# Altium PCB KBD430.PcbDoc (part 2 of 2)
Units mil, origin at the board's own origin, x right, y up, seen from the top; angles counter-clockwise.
Board outline 5000 x 5500 mil, 4 copper layers (Top Layer, Ground Plane, Power Plane, Bottom Layer), stack 90 mil thick; 72 components, 94 nets, 353 pads, 293 vias.
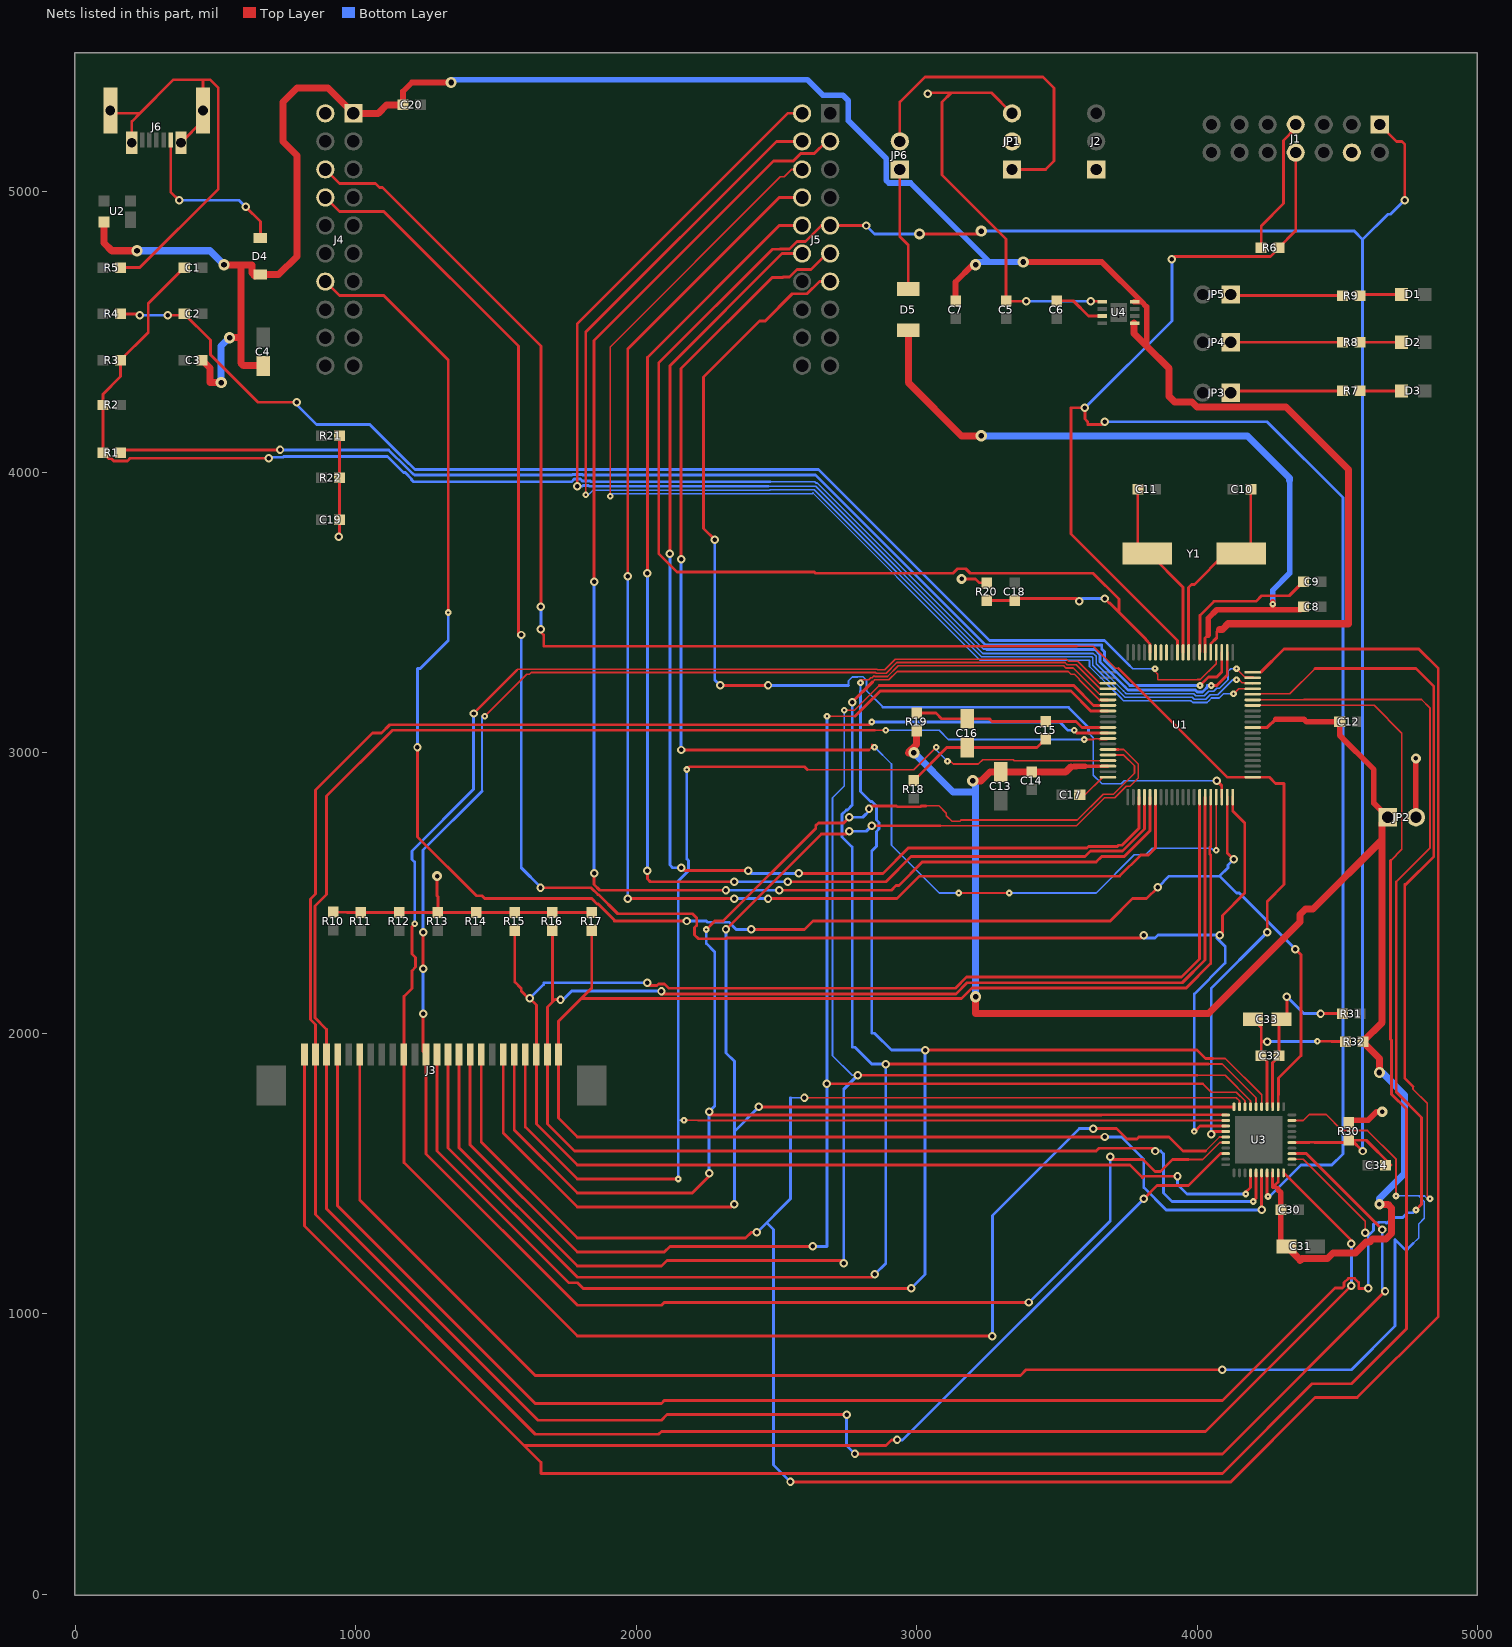
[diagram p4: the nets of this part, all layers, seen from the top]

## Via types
v1: diameter 30, hole 16, Top Layer to Bottom Layer, 176 vias
v2: diameter 24, hole 8, Top Layer to Bottom Layer, 68 vias
v3: diameter 25.98, hole 12.99, Top Layer to Bottom Layer, tented top, 16 vias
v4: diameter 40, hole 20, Top Layer to Bottom Layer, 14 vias
v5: diameter 36, hole 16, Top Layer to Bottom Layer, 13 vias
v6: diameter 32, hole 16, Top Layer to Bottom Layer, 2 vias
v7: diameter 28, hole 16, Top Layer to Bottom Layer, 2 vias
v8: diameter 36, hole 16, Top Layer to Bottom Layer, tented top, 1 vias
v9: diameter 36, hole 16, Top Layer to Bottom Layer, tented both sides, 1 vias

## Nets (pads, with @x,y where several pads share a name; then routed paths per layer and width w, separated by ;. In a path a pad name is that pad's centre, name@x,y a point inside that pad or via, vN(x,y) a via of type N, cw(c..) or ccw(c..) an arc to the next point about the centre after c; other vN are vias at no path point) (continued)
KSI5: J3.22 R15.1 U1.34 U3.34 | length 6521.6
  Top Layer w10: R15.1@1567.14,2367.2 1567.14,2182.86 1590,2160 1590,2150 1615.98,2124.02 v1(1620,2124.02) 1644.02,2100 J3.22@1644.02,1924 1644.02,1675.98 1790,1530 3760,1530 3805,1485 3810,1490 v1(3930,1490) ; v1(2040,2180) 2040,2170 2073.23,2170 2079.23,2176 2100.77,2176 2116.77,2160 3137.37,2160 3177.37,2200 3944.54,2200 4008.9,2264.36 U1.34@4008.9,2842.13 ; v2(4173.38,1426.62) 4170,1430 4190.46,1450.46 U3.34@4190.46,1502.87
  Bottom Layer w10: v1(1620,2124.02) 1670,2174.02 1670,2180 v1(2040,2180) ; v1(3930,1490) 3930,1460 3963.38,1426.62 v2(4173.38,1426.62)
KSI6: J3.23 R16.1 U1.35 U3.35 | length 6490.9
  Top Layer w10: 1701.3,2111.3 R16.1@1701.3,2367.2 ; v1(1730,2120) 1710,2120 1683.39,2093.39 J3.23@1683.39,1924 1683.39,1676.61 1780,1580 3640,1580 3650,1590 3840,1590 v1(3850,1580) ; v1(2090,2150) 2090,2140 3140,2140 3180,2180 3947.16,2180 4028.58,2261.42 U1.35@4028.58,2842.13 ; v2(4200,1400) 4210.15,1410.15 U3.35@4210.15,1502.87
  Bottom Layer w10: v1(1730,2120) 1740,2120 1770,2150 v1(2090,2150) ; 3870,1580 3880,1570 3880,1430 3910,1400 v2(4200,1400)
KSI7: J3.24 R17.1 U1.36 U3.36 | length 6445.5
  Top Layer w10: R17.1@1841.43,2367.2 1841.43,2161.43 1804,2124 ; v1(3670,1630) 1790,1630 1722.76,1697.24 J3.24@1722.76,1924 1722.76,2042.76 1804,2124 ; U1.36@4048.27,2842.13 4048.27,2664.89 4044.95,2661.57 4044.95,2639.21 4048.27,2635.89 4048.27,2248.27 3961,2161 3197.16,2161 3160.16,2124 1804,2124 ; v1(4229.84,1370.16) U3.36@4229.84,1502.87
  Bottom Layer w10: v1(3670,1630) 3730,1630 3810,1550 3810,1450 3890,1370 4200,1370 4200.16,1370.16 v1(4229.84,1370.16)
KSO0: J3.1 U1.54 U3.28 | length 10814
  Top Layer w6: U1.54@4197.87,3168.9 4631.1,3168.9 4730,3070 4730,2655.41 4690,2615.41
  Top Layer w10: J3.1@817.24,1924 817.24,1312.76 1600,530 ; v1(2930,550) 2910,550 2890,530 1600,530 ; v1(3810,1410) 3856.8,1456.8 3969.61,1456.8 4083.6,1570.79 U3.28@4102.87,1570.79 ; 4690,2615.41 4690,1978.67 4693.2,1975.47 4693.2,1782.42 4746.4,1729.22 4746.4,946.4 4550,750 4410,750 4090,430 1660,430 1660,470 1600,530
  Bottom Layer w10: v1(2930,550) 2950,550 v1(3810,1410)
KSO1: J3.2 U1.12 U3.40 | length 9211.2
  Top Layer w10: v2(2840,3110) 2830,3100 1121.33,3100 1091.33,3070 1060,3070 856.61,2866.61 856.61,2496.08 838.53,2477.99 838.53,2048.72 856.61,2030.63 J3.2@856.61,1924 856.61,1353.39 1640,570 2080,570 2090,580 4030,580 v1(4550,1100) ; v2(3561.89,3080) 3570.94,3070.94 3580,3070.94 3580.47,3070.47 U1.12@3682.13,3070.47 ; U3.40@4308.6,1502.87 4550,1261.48 v1(4550,1250)
  Bottom Layer w10: v2(2840,3110) 3510,3110 3540,3080 v2(3561.89,3080) ; v1(4550,1100) v1(4550,1250)
KSO2: J3.3 U1.13 U3.3 | length 9522.9
  Top Layer w6: 2850,3080 v2(2890,3080) ; v2(3597.36,3047.47) 3630.6,3047.47 3633.23,3050.1 3648.97,3050.1 3651.6,3047.47 3678.81,3047.47 U1.13@3682.13,3050.79
  Top Layer w10: v1(2750,640) 2110,640 2090,620 1650,620 895.98,1374.02 J3.3@895.98,1924 895.98,2013.89 854.53,2055.35 854.53,2453.28 895.98,2494.73 895.98,2845.98 1130,3080 2850,3080 ; v1(2780,500) 4090,500 v1(4670,1080) ; U3.3@4337.13,1570.79 4389.21,1570.79 v1(4660,1300)
  Bottom Layer w6: v2(2890,3080) 3080,3080 3112.53,3047.47 v2(3597.36,3047.47)
  Bottom Layer w10: v1(2750,640) 2750,530 v1(2780,500) ; v1(4660,1300) 4660,1090 v1(4670,1080)
KSO3: J3.4 U1.55 U3.2 | length 8064
  Top Layer w6: U1.55@4197.87,3188.58 4378.58,3188.58 4380,3190 4800,3190 4830,3160 4830,2660.06 4709.94,2540 ; U3.2@4337.13,1551.1 4378.9,1551.1 4600,1330 v1(4600,1288.23)
  Top Layer w10: J3.4@935.35,1924 935.35,1384.65 1640,680 2090,680 2100,690 4090,690 4491.31,1091.31 4518.69,1091.31 4524,1096.63 4524,1110.77 4539.23,1126 4560.77,1126 4576,1110.77 4576,1090 v1(4610,1090) ; 4709.94,2540 4709.94,1790.06 4800,1700 4800,1390 v2(4780,1370)
  Bottom Layer w10: v1(4610,1090) 4610,1278.23 4628.57,1296.8 4628.57,1318.57 4633.2,1323.2 4646.43,1323.2 4649.23,1326 4670.77,1326 4673.57,1323.2 4676.41,1323.2 4696.41,1343.2 4733.2,1343.2 4750,1360 4770,1360 v2(4780,1370)
KSO4: J3.6 U1.56 U3.9 | length 8456.1
  Top Layer w6: U1.56@4197.87,3208.27 4199.61,3210 4330,3210 4420,3300 ; U3.9@4337.13,1688.9 4378.9,1688.9 4400,1710 4460.38,1710 4517.57,1652.81 4607.19,1652.81 4709.39,1550.61 v2(4709.39,1419.39) ; 4770,1810 4770,1800 4820,1750 4820,1420 v2(4830,1410)
  Top Layer w10: J3.6@1014.09,1924 1014.09,1405.91 1640,780 3370,780 3390,800 v1(4090,800) ; 4420,3300 4780,3300 4844,3236 4844,2630 4744,2530 4740,2530 4740,1840 4770,1810
  Bottom Layer w6: v2@4719.39,1420 4790,1420 ; 4770,1250 4790,1270 4790,1320 4810,1340 4810,1400 4790.61,1419.39 4810.61,1419.39 4830,1400 v2(4830,1410)
  Bottom Layer w10: v1(4090,800) 4550,800 4706.02,956.02 4706.02,1263.98 4740,1230 4750,1230 4770,1250
KSO5: J3.10 U1.3 U3.25 | length 7908.8
  Top Layer w6: 1572.8,3292.8 1578.03,3298.03 2858.03,3298.03 2860.06,3296 2886,3296 2924,3334 3534,3334 3542,3326 3574,3326 3652.36,3247.64 U1.3@3682.13,3247.64 ; 4030,1580 4079.84,1629.84 U3.25@4102.87,1629.84
  Top Layer w10: v2(1210,2390) 1200,2380 1200,2282.81 1213.2,2269.61 1213.2,2235.62 1200,2222.42 1200,2160 1171.57,2131.57 J3.10@1171.57,1924 1171.57,1538.43 1790,920 v1(3270,920) ; v1(1420,3140) 1572.8,3292.8 ; v1(3630,1660) 3712.81,1660 3749.61,1623.2 3785.47,1623.2 3792.11,1629.84 3900.16,1629.84 3950,1580 4030,1580
  Bottom Layer w10: v2(1210,2390) 1210,2610 1200,2620 1200,2650 1420,2870 v1(1420,3140) ; v1(3270,920) 3270,1350 3580,1660 v1(3630,1660)
KSO6: J3.12 U1.4 U3.26 | length 7505.3
  Top Layer w6: v2(1460,3130) 1610,3280 1619.2,3280 1619.6,3279.6 1626.03,3286.03 2853.06,3286.03 2855.09,3284 2890.97,3284 2928.97,3322 3529.03,3322 3537.03,3314 3569.03,3314 3655.08,3227.95 U1.4@3682.13,3227.95 ; 3968.52,1550 4020,1550 4080.16,1610.16 U3.26@4102.87,1610.16
  Top Layer w10: v1(1240,2070) 1240,1934.32 J3.12@1250.32,1924 1250.32,1569.68 1790,1030 2090,1030 2100,1040 v1(3400,1040) ; v1(1240,2230) v1(1240,2360) ; v1(3690,1560) 3690,1550 3807.19,1550 3850.39,1506.8 3869.61,1506.8 3912.81,1550 3968.52,1550
  Bottom Layer w6: 1450,2862.81 1450,3130 v2(1460,3130)
  Bottom Layer w10: v1(1240,2070) v1(1240,2230) ; v1(1240,2360) 1240,2652.81 1450,2862.81 ; v1(3400,1040) 3690,1330 v1(3690,1560)
KSO7: J3.13 U1.5 U3.15 | length 6879.6
  Top Layer w6: v2(2800,3250) 2800,3260 2829.26,3260 2829.26,3260.17 2836.29,3267.2 2837.4,3267.2 2841.26,3267.2 2848.09,3274.03 2850.12,3272 2895.94,3272 2933.94,3310 3524.06,3310 3532.06,3302 3558,3302 3651.73,3208.27 U1.5@3682.13,3208.27 ; 4056.97,1910 4100,1910 4229.84,1780.16 U3.15@4229.84,1737.13
  Top Layer w10: J3.13@1289.69,1924 1289.69,1580.31 1760,1110 1791.33,1110 1811.33,1090 v1(2980,1090) ; v1(3030,1940) 4000,1940 4030,1910 4056.97,1910
  Bottom Layer w6: 2800,3220 v2(2800,3250)
  Bottom Layer w10: 2800,3220 2800,2861.6 2835.6,2826 2840.77,2826 2856,2810.77 2856,2805.6 2856.4,2805.2 2856.4,2760.37 2866,2750.77 2866,2729.23 2856.5,2719.73 2856.5,2666.5 2840,2650 2840,2000 2850,2000 2910,1940 v1(3030,1940) 3030,1140 v1(2980,1090)
KSO8: J3.14 U1.6 U3.16 | length 6627.1
  Top Layer w6: 2843.2,3253.2 2844.23,3253.2 2851.03,3260 2900.91,3260 2930.91,3290 3540,3290 3550,3280 3563.03,3280 3580,3263.03 3580,3260 3651.42,3188.58 ; 4040,1890 4090,1890 4210.15,1769.85 U3.16@4210.15,1737.13
  Top Layer w10: J3.14@1329.06,1924 1329.06,1590.94 1790,1130 2840,1130 v1(2850,1140) ; v1(2770,3180) 2843.2,3253.2 ; v1(2890,1890) 4040,1890 ; 3651.42,3188.58 U1.6@3682.13,3188.58
  Bottom Layer w10: v1(2770,3180) 2770,2812.81 2753.19,2796 2749.23,2796 2734,2780.77 2734,2776.81 2733.6,2776.41 2733.6,2700 2770,2663.6 2770,1950 2780,1950 2840,1890 v1(2890,1890) 2890,1180 v1(2850,1140)
KSO9: J3.15 U1.7 U3.17 | length 6416.5
  Top Layer w6: v2(2741.6,3151.6) 2778.4,3151.6 2866.8,3240 ; 4000,1850 4100,1850 4190.46,1759.54 U3.17@4190.46,1737.13
  Top Layer w10: J3.15@1368.43,1924 1368.43,1591.57 1790,1170 2090,1170 2110,1190 2730,1190 v1(2740,1180) ; v1(2790,1850) 4000,1850 ; 2866.8,3240 3560,3240 3631.1,3168.9 U1.7@3682.13,3168.9
  Bottom Layer w6: v2(2741.6,3151.6) 2741.6,2881.6 2700,2840 2700,1920 2770,1850 v1(2790,1850)
  Bottom Layer w10: v1(2740,1180) 2740,1800 v1(2790,1850)
KSO10: J3.16 U1.8 U3.18 | length 6257.4
  Top Layer w6: v2(2680,3130) 2780,3130 ; 4020,1820 4050,1790 4140,1790 4170.77,1759.23 U3.18@4170.77,1737.13
  Top Layer w10: J3.16@1407.8,1924 1407.8,1602.2 1790,1220 2100,1220 2120,1240 v1(2630,1240) ; v1(2680,1820) 4020,1820 ; 2780,3130 2870,3220 3550,3220 3620.79,3149.21 U1.8@3682.13,3149.21
  Bottom Layer w6: v2@2680,3120 v2(2680,3130)
  Bottom Layer w10: v1(2630,1240) 2680,1240 v1(2680,1820) v2@2680,3120
KSO11: J3.17 U1.60 U3.19 | length 10129.5
  Top Layer w6: v1(2600,1770) 4140,1770 4151.08,1758.92 U3.19@4151.08,1737.13
  Top Layer w10: J3.17@1447.17,1924 1447.17,1612.83 1790,1270 2390,1270 2410,1290 v1(2430,1290) ; v1(2550,400) 2550,410 2560,400 4120,400 4420.67,700.67 4570.67,700.67 4860,990 4860,3300 4790,3370 4310,3370 U1.60@4227.01,3287.01
  Bottom Layer w6: 2550,1770 v1(2600,1770)
  Bottom Layer w10: v1(2430,1290) 2550,1410 2550,1770 ; 2470,1320 2490,1300 2490,460 v1(2550,400)
KSO12: J3.19 U1.15 U3.20 | length 5900.3
  Top Layer w6: 3084.38,2740 3570,2740 3670,2840 3706.57,2840 3747.23,2880.65 3760.65,2880.65 3790,2910 3790,2960 3738.58,3011.42 3720,3011.42
  Top Layer w10: J3.19@1525.91,1924 1525.91,1644.09 1790,1380 2340,1380 v1(2350,1390) ; v1(2320,2370) 2660,2710 2750,2710 v1(2760,2720) ; v1(2437.13,1737.13) U3.20@4131.39,1737.13 ; v1(2840,2740) 3084.38,2740 ; U1.15@3682.13,3011.42 3720,3011.42
  Bottom Layer w10: v1(2320,2370) 2320,1930 2350,1900 2350,1650 ; v1(2350,1390) 2350,1650 ; v1(2437.13,1737.13) 2350,1650 ; v1(2760,2720) 2820,2720 v1(2840,2740)
KSO13: J3.20 U1.16 U3.21 | length 5801.4
  Top Layer w6: 3032.43,2810.62 3079.38,2810.62 3106,2784 3106,2775.92 3125.92,2756 3154.08,2756 3158.08,2760 3573.03,2760 3665.03,2852 3701.6,2852 3776.51,2926.91 3776.51,2953.49 3738.27,2991.73 U1.16@3682.13,2991.73
  Top Layer w10: J3.20@1565.28,1924 1565.28,1654.72 1790,1430 2200,1430 2260,1490 v1(2260,1500) ; v2(2250,2370) 2280,2400 2310,2400 2640,2730 2640,2740 2650,2750 2740,2750 v1(2760,2770) ; v1(2260,1720) 2260,1710 2261.42,1708.58 3658.44,1708.58 3659.46,1709.6 4101.86,1709.6 U3.21@4102.87,1708.58 ; v1@2833.2,2795.59 2830,2798.79 v1(2830,2800) 2840,2810 2928.52,2810 2930.7,2807.82 3013.26,2807.82 3016.06,2810.62 3032.43,2810.62
  Bottom Layer w10: v2(2250,2370) 2250,2320 2280,2290 2280,1740 v1(2260,1720) v1(2260,1500) ; v1(2760,2770) 2807.61,2770 2833.2,2795.59 2830,2798.79 v1(2830,2800)
KSO14: J3.21 U1.17 U3.22 | length 5915.9
  Top Layer w6: v2(2170,1690) 2220,1690 ; 2240,1690 2220,1690 ; 2610,2940 2990,2940 v2(3070,3020) ; v2(3110,2970) 3120,2970 3130,2960 3220,2960 3235.62,2975.62 3344.38,2975.62 3347.95,2972.05 U1.17@3682.13,2972.05 ; U3.22@4102.87,1688.9 2218.9,1688.9 2220,1690
  Top Layer w10: J3.21@1604.65,1924 1604.65,1665.35 1790,1480 v2(2150,1480) ; v2(2180,2940) 2190,2950 2600,2950 2610,2940
  Bottom Layer w6: 2150,1690 v2(2170,1690) ; v2(3070,3020) 3070,3010 v2(3110,2970)
  Bottom Layer w10: v2(2150,1480) 2150,1690 2150,2543.23 2186,2579.23 2186,2616 2180,2622 v2(2180,2940)
NetC6_2: C6.2 U4.3 | length 188.7
  Top Layer w10: C6.2@3498.72,4611.5 3558.5,4611.5 3612.8,4557.2 U4.3@3664.88,4557.2
NetC15_1: C15.1 C16.1 R19.2 U1.11 | length 703.4
  Top Layer w10: R19.2@3000,3141.5 3068.5,3141.5 3088.82,3121.18 C16.1@3180,3121.18 3258.82,3121.18 3268.5,3111.5 C15.1@3460,3111.5 3568.5,3111.5 3589.84,3090.16 U1.11@3682.13,3090.16
NetC15_2: C15.2 C16.2 R18.2 | length 530.9
  Top Layer w10: R18.2@2990,2901.5 3107.32,3018.82 C16.2@3180,3018.82 3428.82,3018.82 3458.5,3048.5 C15.2@3460,3048.5
NetC32_1: C32.1 C33.1 R32.2 U3.14 | length 624.1
  Top Layer w10: C33.1@4198.82,2050 4228.5,2020.31 4228.5,1970 ; U3.14@4249.53,1750.47 4249.53,1898.97 C32.1@4228.5,1920 4228.5,1970 ; v1(4250,1970) 4228.5,1970 ; v2(4428.74,1971.26) 4478.74,1971.26 4480,1970 R32.2@4528.5,1970
  Bottom Layer w10: v1(4250,1970) 4430,1970 v2(4428.74,1971.26)
NetC32_2: C32.2 C33.2 R31.2 U3.13 | length 637.3
  Top Layer w10: U3.13@4269.22,1737.13 4269.22,1894.78 4291.5,1917.05 C32.2@4291.5,1920 4291.5,2031.5 4301.18,2041.18 C33.2@4301.18,2050 4320,2068.82 v1(4320,2130) ; v1(4440,2070) R31.2@4518.5,2070
  Bottom Layer w10: v1(4320,2130) 4380,2070 v1(4440,2070)
NetD1_1: D1.1 R9.1 | length 148.8
  Top Layer w10: R9.1@4581.5,4630 4585.5,4634 D1.1@4728.66,4634
NetD2_1: D2.1 R8.1 | length 147.2
  Top Layer w10: R8.1@4581.5,4464 D2.1@4728.66,4464
NetD3_1: D3.1 R7.1 | length 153.2
  Top Layer w10: R7.1@4581.5,4290 D3.1@4728.66,4290 D3.1@4734.66,4290
NetD4_2: D4.2 J6.1 | length 607.9
  Top Layer w10: J6.1@340,5185 340,5000 v1(370,4970) ; v1(607,4946.99) 660,4893.99 D4.2@660,4835
  Bottom Layer w10: v1(370,4970) 583.99,4970 v1(607,4946.99)
NetD5_1: D5.1 JP6.1 | length 438.6
  Top Layer w10: JP6.1@2940,5080 2940,4840 2970,4810 D5.1@2970,4653.82
NetJ1_7: J1.7 R6.1 | length 490.9
  Top Layer w10: R6.1@4228.5,4800 4228.5,4878.5 4308.02,4958.02 4308.02,5183.48 4351.5,5226.96 J1.7@4351.5,5240
NetJ6_6: J6.6 J6.7 J6.8 J6.9 R5.2 | length 1602.2
  Top Layer w10: J6.8@134.65,5280 230,5280 ; R5.2@161.5,4730 230,4730 510,5010 510,5370 480,5400 460,5400 ; J6.6@201.5,5175 201.5,5251.5 230,5280 ; J6.7@376.5,5175 J6.9@455.35,5253.85 ; J6.9@455.35,5290 455.35,5395.35 460,5400 ; 230,5280 350,5400 460,5400
NetJP3_1: JP3.1 R7.2 | length 392.5
  Top Layer w10: JP3.1@4126,4290 R7.2@4518.5,4290
NetJP4_1: JP4.1 R8.2 | length 398.5
  Top Layer w10: JP4.1@4120,4464 R8.2@4518.5,4464
NetJP5_1: JP5.1 R9.2 | length 394.5
  Top Layer w10: JP5.1@4124,4630 R9.2@4518.5,4630
PJ.1: U1.73
PJ.2: U1.74
PJ.3: U1.75
PU.0/DP: C1.1 R1.2 R2.2 R3.1 U1.62 | length 5291.5
  Top Layer w10: C1.1@388.5,4730 260,4601.5 260,4498.5 R3.1@161.5,4400 161.5,4341.5 98.5,4278.5 R2.2@98.5,4240 R1.2@98.5,4070 120,4048.5 129.05,4048.5 137.25,4040.3 185.74,4040.3 195.44,4050 v1(690,4050) ; v2(4050,3240) 4070,3240 4107.32,3277.32 U1.62@4107.32,3357.87
  Bottom Layer w6: 2476.63,3966 2636,3966 2640,3962 2644.97,3962 3236.97,3370 3248,3370 3250,3368
  Bottom Layer w10: v1@690,4060 696,4054 740.77,4054 743.57,4056.8 1113.2,4056.8 1170.8,3999.2 1176.24,3999.2 1199.2,3976.24 1199.2,3973.43 1206.63,3966 1769.23,3966 1779.23,3976 1800.77,3976 1807.57,3969.2 1836.24,3969.2 1839.44,3966 2476.63,3966 ; 3250,3368 3635.6,3368 3654,3349.6 3654,3333.37 3654,3323.37 3743.37,3234 3753.37,3224 3993.47,3224 4000.47,3217 4019.53,3217 4026.53,3224 4026.63,3224 4036,3233.37 4036,3240 v2(4050,3240)
PU.1/DM: C2.1 R4.1 U1.64 | length 4558.9
  Top Layer w6: v2@3850,3290 3860,3280 3860,3260 4000.3,3260 4001.3,3261 4011,3261 4067.95,3317.95 U1.64@4067.95,3357.87
  Top Layer w10: R4.1@161.5,4565 225,4565 v1(230,4560) ; v1(330,4560) 383.54,4560 C2.1@388.5,4564.97 482.18,4471.29 482.18,4419.3 651.48,4250 v1(790,4250)
  Bottom Layer w6: 3760,3310 3770,3300 v2(3850,3300)
  Bottom Layer w10: v1(230,4560) v1(330,4560) ; v1(790,4250) 790,4240 860,4170 1050,4170 1188.8,4031.2 1189.49,4031.2 1210.69,4010 2650,4010 3260,3400 3670,3400 3760,3310
PUR: R1.1 U1.63 | length 4395.4
  Top Layer w10: R1.1@161.5,4070 171.5,4080 v1(730,4080) ; v2(4010,3240) 4040,3270 4070,3270 4087.64,3287.64 U1.63@4087.64,3357.87
  Bottom Layer w10: v1(730,4080) 1117.37,4080 1182.17,4015.2 1182.86,4015.2 1204.06,3994 1206,3994 1209.69,3990.31 1770.92,3990.31 1772.6,3992 1807.4,3992 1809.08,3990.31 2639.69,3990.31 3246,3384 3660,3384 3660,3370 3670,3360 3670,3330 3760,3240 v2(4010,3240)
PWM1: J5.3 U1.25 | length 5273.7
  Top Layer w10: v1(1850,2570) 1850,2530 1870,2510 v1(2320,2510) ; v1(1850,3610) 1850,4470 2490,5110 2560.01,5110 2586.53,5136.52 2634.98,5136.52 2678.46,5180 J5.3@2691.5,5180 ; v1(2510,2510) 2910,2510 2926.8,2526.8 2936.8,2526.8 3020,2610 3640,2610 3660,2630 3740,2630 3831.73,2721.73 U1.25@3831.73,2842.13
  Bottom Layer w10: v1(1850,2570) v1(1850,3610) ; v1(2320,2510) v1(2510,2510)
PWM2: J5.8 U1.26 | length 4956.6
  Top Layer w10: v1(1970,2480) 1970,2490 1980,2480 v1(2350,2480) ; v1(1970,3630) 1970,4440 2510,4980 J5.8@2591.5,4980 ; v1(2470,2480) 2930,2480 3010,2560 3723.23,2560 3799.23,2636 3826,2636 3851.42,2661.42 U1.26@3851.42,2842.13
  Bottom Layer w10: v1(1970,2480) v1(1970,3630) ; v1(2350,2480) v1(2470,2480)
PWM3: J5.6 U1.57 | length 4118.8
  Top Layer w6: v2@1907,3913 v2(1907,3915) 1907,4446.8 2513.52,5053.32 2527.32,5053.32 2554,5080 J5.6@2591.5,5080 ; v2(4130,3210) 4147.95,3227.95 U1.57@4197.87,3227.95
  Bottom Layer w6: v2(1907,3915) 1916,3924 2628.06,3924 2630.06,3926 3226.06,3330 3616,3330 3616,3317.63 3616,3307.63 3727.63,3196 3737.63,3186 3977.73,3186 3984.73,3179 4035.27,3179 4042.27,3186 4042.37,3186 4051.37,3195 4078.94,3195 4093.94,3210 v2(4130,3210)
PWM4: J5.4 U1.58 | length 4370
  Top Layer w6: v2(1820,3920) 1820,3970 ; v2(4140,3260) 4150,3260 4160,3250 U1.58@4190,3250 ; U1.58@4196.56,3246.32 U1.58@4197.87,3247.64
  Top Layer w10: 1820,3970 1820,4500 2500,5180 J5.4@2591.5,5180
  Bottom Layer w6: v2(1820,3920) 1830,3920 1846,3936 2475.8,3936 2477.8,3938 2635.03,3938 3231.03,3342 3624.83,3342 3628,3338.83 3628,3322.6 3628,3312.6 3732.6,3208 3742.6,3198 3982.7,3198 3989.7,3191 4030.3,3191 4037.3,3198 4037.4,3198 4046.4,3207 4063.67,3207 4073.97,3207 4126.97,3260 v2(4140,3260)
PWM5: J5.2 U1.59 | length 4485.6
  Top Layer w6: 4150,3290 4170,3270 U1.59@4200,3270
  Top Layer w10: v1(1790,3950) 1790,4530 2540,5280 J5.2@2591.5,5280
  Bottom Layer w6: 2470,3950 2640,3950 3236,3354 3629.8,3354 3640,3343.8 3640,3327.57 3640,3317.57 3737.57,3220 3747.57,3210 3987.67,3210 3994.67,3203 4025.33,3203 4032.33,3210 4032.43,3210 4041.43,3219 4058.7,3219 4069.7,3230 4080,3230 4110,3260 4110,3290 4120,3300 v2(4140,3300)
  Bottom Layer w10: v1(1790,3950) 1807.19,3950 1810.39,3953.2 1829.61,3953.2 1832.81,3950 2470,3950
RST/SBWTDIO: C18.1 C34.1 J1.1 J5.9 R20.1 R30.1 U1.76 U3.5 | length 10103.6
  Top Layer w10: v1(2820,4880) J5.9@2691.5,4880 2660,4880 2603.48,4823.48 2573.49,4823.48 2546.01,4796 2513.37,4796 2512.37,4795 2485,4795 2080,4390 2080,3710 2146,3644 2146.8,3644.8 2550.74,3644.8 2551.54,3644 2635.8,3644 2639.8,3640 3129.09,3640 3145.09,3656 3174.91,3656 3190.91,3640 3629.2,3640 3721.11,3548.08 3721.11,3501.11 ; v4(3010,4850) 3220,4850 v4(3230,4860) ; R20.1@3250,3542.95 C18.1@3350,3542.95 3357.05,3550 3570,3550 v1(3580,3540) ; v1(3670,3550) 3686,3534 3688.23,3534 3721.11,3501.11 ; U1.76@3831.73,3357.87 3831.73,3388.27 3816.68,3403.32 3816.68,3405.55 3721.11,3501.11 ; U3.5@4337.13,1610.16 4399.52,1610.16 4400.83,1611.47 4418.23,1611.47 4419.54,1610.16 4531.65,1610.16 R30.1@4540,1618.5 R30.1@4551.5,1618.5 ; v1(4590,1580) R30.1@4551.5,1618.5 ; J1.1@4651.5,5240 4711.5,5180 4730,5180 4740,5170 v1(4740,4970) ; 4691.5,1530 4602.99,1618.5 R30.1@4551.5,1618.5
  Bottom Layer w10: v1@2823.2,4876.8 2850,4850 v4(3010,4850) ; v4(3230,4860) 4560,4860 4590,4830 ; v1(3580,3540) 3590,3550 v1(3670,3550) ; v1(4590,1580) 4590,4830 ; v1(4740,4970) 4690,4920 4680,4920 4590,4830
SBWTCK: J1.8 R6.2 U1.71 U3.37 | length 6348.9
  Top Layer w10: v1(3670,4180) 3660,4170 3610,4170 3610,4180 3600,4190 v1(3600,4230) 3550,4230 3550,3780 3930.16,3399.84 U1.71@3930.16,3357.87 ; v1(3910,4760) 3920,4770 4261.5,4770 R6.2@4291.5,4800 4291.5,4801.5 4350,4860 4351.5,4860 J1.8@4351.5,5140 ; U3.37@4249.53,1502.87 4249.53,1420.87 v2(4252.84,1417.56)
  Bottom Layer w10: v1(3600,4230) 3910,4540 v1(3910,4760) ; v1(3670,4180) 4250,4180 4520,3910 4520,1570 4480,1530 4370,1530 4257.56,1417.56 v2(4252.84,1417.56)
SPI_CLK: J4.14 U1.39 U3.12 | length 6678.3
  Top Layer w10: J4.14@891.5,4680 941.5,4630 1100,4630 1330,4400 v2(1330,3500) ; v1(1220,3020) 1220,2700 1430,2490 1450,2490 1460,2480 1841.61,2480 1860.73,2460.88 1864.69,2460.88 1921.61,2403.96 1921.61,2400 v1(2180,2400) ; v1(2410,2370) 2600,2370 2630,2400 3690,2400 3770,2480 3820,2480 v1(3860,2520) ; U1.39@4107.32,2842.13 4107.32,2642.68 v1(4130,2620) ; U3.12@4288.91,1737.13 4288.91,1778.91 4290,1780 4290,1840 4370,1920 4370,2280 v1(4350,2300)
  Bottom Layer w10: v1(1220,3020) 1220,3300 1230,3300 1330,3400 v2(1330,3500) ; v1(2180,2400) 2250,2400 2254,2396 2330.77,2396 2356.77,2370 v1(2410,2370) ; v1(3860,2520) 3900,2560 4080,2560 ; v1(4130,2620) 4110,2600 4110,2590 4080,2560 ; v1(4350,2300) 4150,2500 4140,2500 4080,2560
SPI_MISO: J5.13 U1.38 | length 3845.3
  Top Layer w10: v1(2280,3760) 2240,3800 2240,4340 2440,4540 2460,4540 2556.52,4636.52 2609.51,4636.52 2652.99,4680 J5.13@2691.5,4680 ; v1(2300,3240) v1(2470,3240) ; v1(4070,2900) 4087.64,2882.36 U1.38@4087.64,2842.13
  Bottom Layer w6: 2757.19,3240 2757.19,3257.19 2770,3270 2790.3,3270 2791.3,3271 2808.7,3271 2821,3258.7 2821,3221.35 2880.39,3161.96 ; 3613.2,3070.39 3630,3053.59 3630,2920 3657.64,2892.36 ; 3660,2890 3730,2890 3740,2900 v1(4070,2900)
  Bottom Layer w10: v1(2280,3760) 2280,3260 v1(2300,3240) ; v1(2470,3240) 2757.19,3240 ; 2880.39,3161.96 3540.85,3161.96 3613.2,3089.61 3613.2,3070.39
SPI_MOSI: J5.11 U1.37 | length 4632.5
  Top Layer w6: 2830,3010 2840,3020 2840,3030 v2(2850,3020) ; v2(3150,2500) v2(3330,2500) ; v2(4067.95,2652.05) U1.37@4067.95,2842.13
  Top Layer w10: v1(2160,3010) 2340,3010 2830,3010 ; v1(2160,3690) 2160,4370 2485,4695 2522.37,4695 2523.37,4696 2546.01,4696 2573.49,4723.48 2623.48,4723.48 2680,4780 J5.11@2691.5,4780
  Bottom Layer w6: v2(2850,3020) 2910,2960 2910,2670 3080,2500 v2(3150,2500) ; v2(3330,2500) 3640,2500 3776,2636 3816,2636 3840,2660 4050,2660 4057.95,2652.05 v2(4067.95,2652.05)
  Bottom Layer w10: v1(2160,3010) v1(2160,3690)
TCAP1: J5.12 U1.23 | length 4279.8
  Top Layer w10: v1(2120,3710) 2120,4380 2520,4780 J5.12@2591.5,4780 ; v1(2160,2590) 2170,2580 v1(2400,2580) ; v1(2580,2570) 2880,2570 2970,2660 3607.29,2660 3613.29,2666 3716,2666 3720,2670 3731.47,2670 3792.36,2730.89 U1.23@3792.36,2842.13
  Bottom Layer w10: v1(2120,3710) 2120,2600 2130,2590 v1(2160,2590) ; v1(2400,2580) 2410,2570 v1(2580,2570)
TCAP2: J5.10 U1.24 | length 4584.4
  Top Layer w10: v1(2040,2580) 2040,2550 2050,2540 v1(2350,2540) ; v1@2040,3630 v1(2040,3640) 2040,4410 2510,4880 J5.10@2591.5,4880 ; v1(2540,2540) 2890,2540 2980,2630 3599.92,2630 3619.92,2650 3734.1,2650 3812.05,2727.95 U1.24@3812.05,2842.13
  Bottom Layer w10: v1(2040,2580) v1(2040,3640) ; v1(2350,2540) v1(2540,2540)
UART_RX: J4.6 U1.41 U3.24 | length 6377.3
  Top Layer w6: 3570,3380 3630,3380 3709.07,3300.93 3719.13,3300.93 3719.85,3300.21
  Top Layer w10: J4.6@891.5,5080 941.5,5030 1070,5030 1085,5015 1095,5015 1660,4450 v1(1660,3520) ; v1(1660,3440) 1660,3430 1670,3420 1670,3380 3570,3380 ; 3719.85,3300.21 4107.07,2912.99 U1.41@4197.87,2912.99 4257.01,2912.99 4280,2890 4310,2890 4310,2530 4250,2470 v1(4250,2360) ; v1(4050,1640) 4049.53,1640.47 4049.53,1649.53 U3.24@4102.87,1649.53
  Bottom Layer w10: v1@1660,3430 v1(1660,3440) v1(1660,3520) ; v1(4050,1640) 4050,2160 v1(4250,2360)
UART_TX: J4.8 U1.40 U3.23 | length 6870.4
  Top Layer w10: J4.8@891.5,4980 941.5,4930 1100,4930 1580,4450 1580,3420 v1(1590,3420) ; v1(1658.72,2518.72) 1838.65,2518.72 1863.37,2494 1866,2494 1934,2426 2200.77,2426 2216,2410.77 2216,2384 2208.31,2376.31 2208.31,2350.39 2221.9,2336.8 2319.61,2336.8 2322.81,2340 3800,2340 v1(3810,2350) ; v2(3990,1650) 3991.57,1650 4010.79,1669.21 U3.23@4102.87,1669.21 ; v1(4080,2350) 4090,2360 4090,2420 4170,2500 4170,2750 4127.01,2792.99 U1.40@4127.01,2842.13
  Bottom Layer w10: v1(1590,3420) 1590,2590 1658.72,2521.28 v1(1658.72,2518.72) ; v1(3810,2350) 3810,2340 3850,2340 3860,2350 v1(4080,2350) 4070,2340 4100,2310 4100,2250 3990,2140 v2(3990,1650)
V18: C9.1 U1.67 | length 550.8
  Top Layer w10: U1.67@4008.9,3357.87 4010,3358.98 4010,3490 4060,3540 4210,3540 4230,3560 4328.5,3560 C9.1@4378.5,3610
VBUS: C3.1 C4.1 C7.1 C20.2 D4.1 J4.1 U1.65 U2.4 U4.5 U4.8 | length 8357.7
  Top Layer w10: 4048.27,3388.27 4070,3410 4070,3430 4080,3440
  Top Layer w20: C20.2@1168.5,5310 1168.5,5358.5 1200,5390 v4(1340,5390) ; C7.1@3138.46,4611.5 3138.46,4678.46 3200,4740 v4(3210,4740) ; v4(3380,4750) 3660,4750 3801.61,4608.39 ; U4.8@3775.12,4608.39 3801.61,4608.39 ; 3820,4450 3820,4590 3801.61,4608.39
  Top Layer w25: U2.4@102.76,4892.2 102.76,4817.24 130,4790 v4(220,4790) ; C3.1@451.5,4400 480,4371.5 480,4320 v4(520,4320) ; v4(530,4740) 590,4740 ; v4(550,4480) 590,4480 ; D4.1@640,4700 630,4710 630,4740 590,4740 ; D4.1@660,4705 725,4705 790,4770 790,5130 740,5180 740,5320 790,5370 901.5,5370 J4.1@991.5,5280 1080,5280 1110,5310 C20.2@1168.5,5310 ; C4.1@670,4380 600,4380 590,4390 590,4480 ; U4.5@3775.12,4531.61 3775.12,4494.88 3820,4450 3900.5,4369.5 3900.5,4270.12 3920.12,4250.5 3981.4,4250.5 3998.88,4233.02 4316.98,4233.02 4540,4010 4540,3460 4110,3460 4090,3440 4080,3440 ; 590,4480 590,4740
  Bottom Layer w20: v4(1340,5390) 1340,5400 2610,5400 2665.52,5344.48 2737.23,5344.48 2755.98,5325.74 2755.98,5254.02 2891.52,5118.48 2891.52,5040.89 2900.89,5031.52 2978.48,5031.52 3260,4750 ; v4(3210,4740) 3220,4750 3260,4750 ; v4(3380,4750) 3260,4750
  Bottom Layer w25: v4(220,4790) 480,4790 v4(530,4740) ; v4(520,4320) 520,4450 v4(550,4480)
VBUS_LDO: C5.1 JP1.3 U4.1 | length 1527.9
  Top Layer w10: v1(3040,5350) 3043.5,5353.5 3123.5,5353.5 ; C5.1@3318.59,4611.5 3318.59,4831.41 3090,5060 3090,5320 3123.5,5353.5 ; C5.1@3320.09,4610 v1(3390,4610) ; JP1.3@3340,5280 3266.5,5353.5 3123.5,5353.5 ; v1(3620,4610) 3663.27,4610 U4.1@3664.88,4608.39
  Bottom Layer w10: v1(3390,4610) v1(3620,4610)
VCC: C19.2 J1.4 J2.1 J4.2 JP1.2 JP2.2 R10.2 R11.2 R12.2 R13.2 R14.2 R15.2 R16.2 R17.2 R20.2 R21.1 R22.1 R30.2 | length 1838.8
  Top Layer w10: R10.2@920,2431.5 968.5,2431.5 969.8,2430.2 R11.2@1018.57,2430.2 R12.2@1155.71,2430.2 R13.2@1289.8,2430.2 ; v1(940,3770) 941.5,3771.5 C19.2@941.5,3830 R22.1@941.5,3980 R21.1@941.5,4130 ; v5(1290,2560) 1290,2490 1292.86,2487.14 R13.2@1292.86,2430.2 R14.2@1430,2430.2 R15.2@1567.14,2430.2 R16.2@1701.3,2430.2 R17.2@1841.43,2430.2 ; v5(3160,3620) 3210,3620 3224.06,3605.94 R20.2@3250,3605.94
  Top Layer w20: R30.2@4550,1690 4610,1690 4640,1720 v5(4660,1720) ; JP2.2@4780,2770 v5(4780,2980)
VCC430: C12.1 C13.1 C14.1 C30.1 C31.1 JP2.1 R19.1 R32.1 U1.18 U1.50 U3.38 U3.39 | length 6610.8
  Top Layer w10: U3.38@4269.22,1502.87 4269.22,1460 ; U3.39@4288.91,1502.87 4288.91,1468.91 4280,1460 4269.22,1460 ; 4290,1450 4269.22,1450 4269.22,1460
  Top Layer w12: 3600,2952.36 U1.18@3682.13,2952.36 ; U1.50@4197.87,3090.16 4250.16,3090.16 4280,3120
  Top Layer w20: 3550,2950 3560,2950 ; 3570,2950 3560,2950 ; 3600,2952.36 3562.36,2952.36 3560,2950 ; 4280,3120 4380,3120 4390,3110 C12.1@4508.5,3110 4508.5,3061.5 4630,2940 4630,2820 JP2.1@4680,2770 ; 4288.91,1441.09 4298.5,1431.5 C30.1@4298.5,1370 4298.5,1260.31 C31.1@4318.82,1240
  Top Layer w25: v4(2990,3000) 2970,3000 3000,3030 R19.1@3000,3078.5 ; v4(3200,2900) 3230,2900 3261.18,2931.18 C13.1@3300,2931.18 3409.69,2931.18 C14.1@3410,2931.5 3531.5,2931.5 3550,2950 ; v4(3210,2130) 3210,2070 4040,2070 4366.5,2396.5 4366.5,2423.88 4386.12,2443.5 4413.5,2443.5 4660,2690 ; C31.1@4318.82,1240 4367.64,1191.18 4367.64,1190 4374.53,1196.89 4464.28,1196.89 4483.88,1216.5 4563.88,1216.5 4602.1,1254.73 4613.88,1254.73 4625.65,1266.5 4673.88,1266.5 4693.5,1286.12 4693.5,1376.5 4680,1390 v5(4650,1390) ; v4(4650,1860) 4650,1910 4591.5,1968.5 R32.1@4591.5,1970 4660,2038.5 4660,2690 ; JP2.1@4660,2750 4660,2690
  Bottom Layer w25: v4(2990,3000) 3130,2860 3210,2860 ; v4(3200,2900) 3210,2890 3210,2860 ; v4(3210,2130) 3210,2860 ; v5(4650,1390) 4650,1410 4740,1500 4740,1780 4660,1860 v4(4650,1860)
VCORE: C17.1 U1.20 | length 126.7
  Top Layer w6: C17.1@3581.5,2850 3600,2850 3662.99,2912.99 U1.20@3682.13,2912.99
VUSB: C8.1 D5.2 U1.66 | length 2672.8
  Top Layer w10: U1.66@4028.58,3357.87 4028.58,3408.58 4040,3420
  Top Layer w20: 4040,3420 4040,3480 4070,3510 4270,3510 ; v2@4270,3539 v2(4270,3530) 4270,3510 ; C8.1@4378.5,3520 4368.5,3510 4270,3510
  Top Layer w25: D5.2@2970,4506.18 2970,4320 3160,4130 v4(3230,4130)
  Bottom Layer w20: v2(4270,3530) 4270,3580 4330,3640 4330,3970
  Bottom Layer w25: v4(3230,4130) 4180,4130 4330,3980 4330,3970
VUSB_VCC: JP1.1 JP6.2 | length 1166.3
  Top Layer w10: JP6.2@2940,5180 2940,5320 3030,5410 3450,5410 3490,5370 3490,5110 3460,5080 JP1.1@3340,5080
XT2IN: C10.2 U1.69 Y1.1 | length 713.5
  Top Layer w10: U1.69@3969.53,3357.87 3969.53,3589.53 3980,3600 3990,3600 4100,3710 Y1.1@4157.32,3710 4191.5,3744.17 C10.2@4191.5,3940
XT2OUT: C11.2 U1.70 Y1.2 | length 653.2
  Top Layer w10: C11.2@3788.5,3940 3788.5,3744.17 Y1.2@3822.68,3710 3830,3710 3949.84,3590.16 U1.70@3949.84,3357.87
pads on no net: J1.2 J1.3 J1.5 J1.6 J1.10 J1.11 J1.12 J1.13 J1.14 J3.7 J3.25 J3.26 J6.4 U4.2 U4.6 U4.7

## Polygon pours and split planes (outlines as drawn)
GND on Top Layer "Top Layer-No Net 1" (solid, remove dead copper, pour order 10): 20,5460 40,5440 4950,5440 4950,40 4930,60 20,60
GND on Bottom Layer "Bottom Layer-No Net" (solid, remove dead copper, pour order 12): 30,5480 4980,5480 4970,5470 4970,20 30,20
GND on Ground Plane (split plane): 4977.9,16.1 18.1,16.1 18.1,5475.9 4977.9,5475.9
VCC on Power Plane (split plane): 4977.9,16.1 18.1,16.1 18.1,5475.9 4977.9,5475.9

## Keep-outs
Keep-Out Layer:
  lines w10: 48,46 48,5446 4948,5446 4948,46 48,46

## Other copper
Top Layer:
  pour cut-out: 3930,3410 3640,3700 3650,3720 3940,3430
  pour cut-out: 3700,4080 3650,4080 3650,3710 3660,3680 3700,3660
  pour cut-out: 3650,4100 4330,4100 4330,4070 3650,4070
  pour cut-out: 4330,4100 4330,3620 4270,3580 4270,4090
  pour cut-out: 4330,3620 4300,3590 4300,3570 4220,3570 4200,3550 4110,3550 4110,3570 4190,3570 4210,3590 4280,3590 4310,3620
  pour cut-out: 4110,3570 4050,3570 4010,3530 4020,3520 4050,3550 4110,3550
  pour cut-out: 3770,4080 3680,3990 3670,4000 3670,4090 3770,4090
  pour cut-out: 4190,4080 4290,3980 4300,3980 4300,4070 4290,4080
  pour cut-out: 4280,3640 4210,3570 4260,3570 4280,3590
Ground Plane (plane layer: these items are gaps in the copper):
  pour cut-out: 3680,3990 3760,4070 4200,4070 4290,3980 4290,3650 4190,3550 4050,3550 4000,3500 4000,3320 3930,3320 3930,3410 3680,3660
Power Plane (plane layer: these items are gaps in the copper):
  pour cut-out: 3680,3990 3680,3660 3930,3410 3930,3330 3940,3320 4000,3320 4000,3500 4050,3550 4190,3550 4290,3650 4290,3980 4200,4070 3760,4070

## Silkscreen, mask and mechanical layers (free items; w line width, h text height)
Top Overlay:
  region: 415 vertices and 4 holes, not listed, extent 1615.09,4565.09 1971.51,4888.51
  text "USB" at 550,5280 h40
  text "GND" at 3710,5260 h40
  text "LDO" at 3420,5250 h40
  text "GND" at 3710,5160 h40
  text "Keyboard TI Design - MSP430" at 1210,5110 h40
  text "VUSB" at 3050,5060 h40 r90
  text "VUSB" at 3420,5050 h40
  text "VCC" at 3710,5020 h40
  text "JTAG" at 4670,4920 h40
  text "Rev 1.0" at 4630,160 h40
  text "HH-LR" at 4690,90 h40
M2 Board Dimensions:
  rectangle: 70,-455.5 195,-330.5
  rectangle: 195,-580.5 570,-455.5
Drill Drawing:
  text ".LEGEND" at 5198,196 h60
  text "Drill Drawing." at 5198,96 h60

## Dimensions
48,46 to 48,5446 on M1 Board Outline
48,46 to 4948,46 on M1 Board Outline
70,-580.5 to 1070,-580.5 on M2 Board Dimensions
